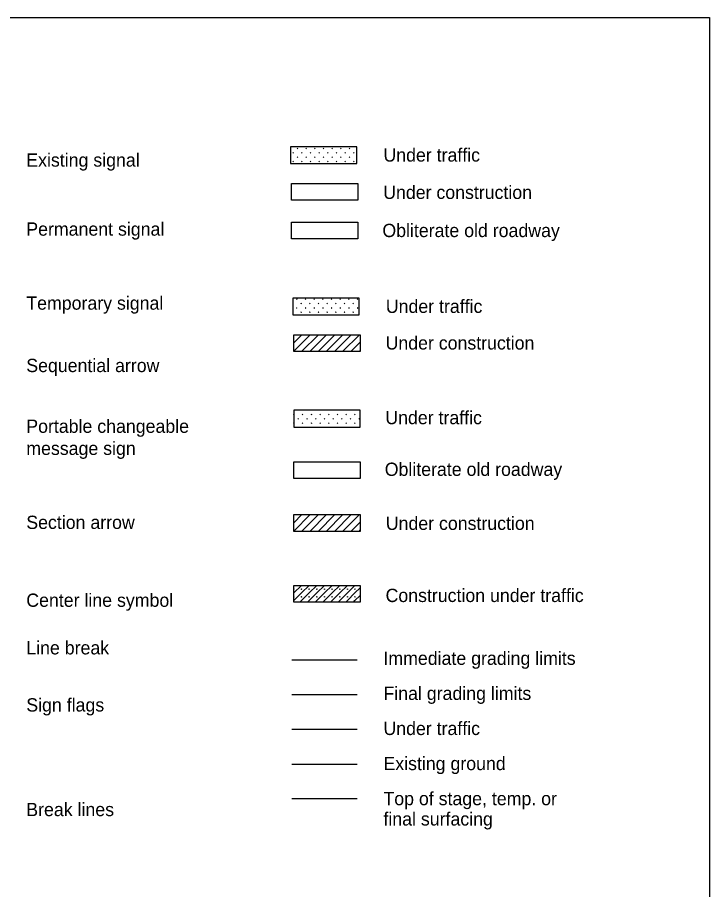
# Model space of a CAD drawing. Extents: x 1458 to 4498, y 17709 to 24109.
# Drawn here: x 3716 to 4498, y 18723 to 19709 of the extents above; entities that cross this region are included whole.
import ezdxf

# ---------------------------------------------------------------- set-up
doc = ezdxf.new("R2010")
doc.units = 0
doc.layers.add('P_TRAF_TCP_General', color=7, linetype='Continuous')
doc.layers.add('P_TRAF_TCP_GeneralTx', color=7, linetype='Continuous')

msp = doc.modelspace()

# ---------------------------------------------------------------- linework, layer by layer
at = {"layer": 'P_TRAF_TCP_General'}
for p, q in [((4027.54, 19555.92), (4027.19, 19556.28)), ((4027.54, 19555.92), (4027.19, 19555.57)), ((4027.54, 19555.92), (4027.89, 19556.28)), ((4027.54, 19555.92), (4027.89, 19555.57)), ((4032.11, 19561.2), (4032.81, 19560.49)), ((4032.81, 19561.2), (4032.11, 19560.49)), ((4037.38, 19555.92), (4037.03, 19556.28)), ((4037.38, 19555.92), (4037.03, 19555.57)), ((4037.38, 19555.92), (4037.73, 19556.28)), ((4037.38, 19555.92), (4037.73, 19555.57)), ((4041.95, 19561.2), (4042.65, 19560.49)), ((4042.65, 19561.2), (4041.95, 19560.49)), ((4047.22, 19555.92), (4046.87, 19556.28)), ((4047.22, 19555.92), (4046.87, 19555.57)), ((4047.22, 19555.92), (4047.57, 19556.28)), ((4047.22, 19555.92), (4047.57, 19555.57)), ((4051.78, 19561.2), (4052.49, 19560.49)), ((4052.49, 19561.2), (4051.78, 19560.49)), ((4057.06, 19555.92), (4056.7, 19556.28)), ((4057.06, 19555.92), (4056.7, 19555.57)), ((4057.06, 19555.92), (4057.41, 19556.28)), ((4057.06, 19555.92), (4057.41, 19555.57)), ((4061.62, 19561.2), (4062.33, 19560.49)), ((4062.33, 19561.2), (4061.62, 19560.49)), ((4066.9, 19555.92), (4066.54, 19556.28)), ((4066.9, 19555.92), (4066.54, 19555.57)), ((4066.9, 19555.92), (4067.25, 19556.28)), ((4066.9, 19555.92), (4067.25, 19555.57)), ((4071.46, 19561.2), (4072.17, 19560.49)), ((4072.17, 19561.2), (4071.46, 19560.49)), ((4076.73, 19555.92), (4076.38, 19556.28)), ((4076.73, 19555.92), (4076.38, 19555.57)), ((4076.73, 19555.92), (4077.09, 19556.28)), ((4076.73, 19555.92), (4077.09, 19555.57)), ((4081.3, 19561.2), (4082.01, 19560.49)), ((4082.01, 19561.2), (4081.3, 19560.49)), ((4086.57, 19555.92), (4086.22, 19556.28)), ((4086.57, 19555.92), (4086.22, 19555.57)), ((4086.57, 19555.92), (4086.93, 19556.28)), ((4086.57, 19555.92), (4086.93, 19555.57)), ((4091.14, 19561.2), (4091.85, 19560.49)), ((4091.85, 19561.2), (4091.14, 19560.49)), ((4096.41, 19555.92), (4096.06, 19556.28)), ((4096.41, 19555.92), (4096.06, 19555.57)), ((4096.41, 19555.92), (4096.76, 19556.28)), ((4096.41, 19555.92), (4096.76, 19555.57)), ((4027.54, 19546.09), (4027.19, 19546.44)), ((4027.54, 19546.09), (4027.19, 19545.73)), ((4027.54, 19546.09), (4027.89, 19546.44)), ((4027.54, 19546.09), (4027.89, 19545.73)), ((4032.11, 19551.36), (4032.81, 19550.65)), ((4032.81, 19551.36), (4032.11, 19550.65)), ((4037.38, 19546.09), (4037.03, 19546.44)), ((4037.38, 19546.09), (4037.03, 19545.73)), ((4037.38, 19546.09), (4037.73, 19546.44)), ((4037.38, 19546.09), (4037.73, 19545.73)), ((4041.95, 19551.36), (4042.65, 19550.65)), ((4042.65, 19551.36), (4041.95, 19550.65)), ((4047.22, 19546.09), (4046.87, 19546.44)), ((4047.22, 19546.09), (4046.87, 19545.73)), ((4047.22, 19546.09), (4047.57, 19546.44)), ((4047.22, 19546.09), (4047.57, 19545.73)), ((4051.78, 19551.36), (4052.49, 19550.65)), ((4052.49, 19551.36), (4051.78, 19550.65)), ((4057.06, 19546.09), (4056.7, 19546.44)), ((4057.06, 19546.09), (4056.7, 19545.73)), ((4057.06, 19546.09), (4057.41, 19546.44)), ((4057.06, 19546.09), (4057.41, 19545.73)), ((4061.62, 19551.36), (4062.33, 19550.65)), ((4062.33, 19551.36), (4061.62, 19550.65)), ((4066.9, 19546.09), (4066.54, 19546.44)), ((4066.9, 19546.09), (4066.54, 19545.73)), ((4066.9, 19546.09), (4067.25, 19546.44)), ((4066.9, 19546.09), (4067.25, 19545.73)), ((4071.46, 19551.36), (4072.17, 19550.65)), ((4072.17, 19551.36), (4071.46, 19550.65)), ((4076.73, 19546.09), (4076.38, 19546.44)), ((4076.73, 19546.09), (4076.38, 19545.73)), ((4076.73, 19546.09), (4077.09, 19546.44)), ((4076.73, 19546.09), (4077.09, 19545.73)), ((4081.3, 19551.36), (4082.01, 19550.65)), ((4082.01, 19551.36), (4081.3, 19550.65)), ((4086.57, 19546.09), (4086.22, 19546.44)), ((4086.57, 19546.09), (4086.22, 19545.73)), ((4086.57, 19546.09), (4086.93, 19546.44)), ((4086.57, 19546.09), (4086.93, 19545.73)), ((4091.14, 19551.36), (4091.85, 19550.65)), ((4091.85, 19551.36), (4091.14, 19550.65)), ((4096.41, 19546.09), (4096.06, 19546.44)), ((4096.41, 19546.09), (4096.06, 19545.73)), ((4096.41, 19546.09), (4096.76, 19546.44)), ((4096.41, 19546.09), (4096.76, 19545.73)), ((4031.3, 19390.81), (4032, 19390.11)), ((4032, 19390.81), (4031.3, 19390.11)), ((4041.14, 19390.81), (4041.84, 19390.11)), ((4041.84, 19390.81), (4041.14, 19390.11)), ((4050.97, 19390.81), (4051.68, 19390.11)), ((4051.68, 19390.81), (4050.97, 19390.11)), ((4060.81, 19390.81), (4061.52, 19390.11)), ((4061.52, 19390.81), (4060.81, 19390.11)), ((4070.65, 19390.81), (4071.36, 19390.11)), ((4071.36, 19390.81), (4070.65, 19390.11)), ((4080.49, 19390.81), (4081.2, 19390.11)), ((4081.2, 19390.81), (4080.49, 19390.11)), ((4090.33, 19390.81), (4091.04, 19390.11)), ((4091.04, 19390.81), (4090.33, 19390.11)), ((4100.17, 19390.81), (4100.87, 19390.11)), ((4100.87, 19390.81), (4100.17, 19390.11)), ((4031.3, 19380.97), (4032, 19380.27)), ((4032, 19380.97), (4031.3, 19380.27)), ((4036.57, 19385.54), (4036.22, 19385.89)), ((4036.57, 19385.54), (4036.22, 19385.19)), ((4036.57, 19385.54), (4036.92, 19385.89)), ((4036.57, 19385.54), (4036.92, 19385.19)), ((4041.14, 19380.97), (4041.84, 19380.27)), ((4041.84, 19380.97), (4041.14, 19380.27)), ((4046.41, 19385.54), (4046.06, 19385.89)), ((4046.41, 19385.54), (4046.06, 19385.19)), ((4046.41, 19385.54), (4046.76, 19385.89)), ((4046.41, 19385.54), (4046.76, 19385.19)), ((4050.97, 19380.97), (4051.68, 19380.27)), ((4051.68, 19380.97), (4050.97, 19380.27)), ((4056.25, 19385.54), (4055.89, 19385.89)), ((4056.25, 19385.54), (4055.89, 19385.19)), ((4056.25, 19385.54), (4056.6, 19385.89)), ((4056.25, 19385.54), (4056.6, 19385.19)), ((4060.81, 19380.97), (4061.52, 19380.27)), ((4061.52, 19380.97), (4060.81, 19380.27)), ((4066.09, 19385.54), (4065.73, 19385.89)), ((4066.09, 19385.54), (4065.73, 19385.19)), ((4066.09, 19385.54), (4066.44, 19385.89)), ((4066.09, 19385.54), (4066.44, 19385.19)), ((4070.65, 19380.97), (4071.36, 19380.27)), ((4071.36, 19380.97), (4070.65, 19380.27)), ((4075.92, 19385.54), (4075.57, 19385.89)), ((4075.92, 19385.54), (4075.57, 19385.19)), ((4075.92, 19385.54), (4076.28, 19385.89)), ((4075.92, 19385.54), (4076.28, 19385.19)), ((4080.49, 19380.97), (4081.2, 19380.27)), ((4081.2, 19380.97), (4080.49, 19380.27)), ((4085.76, 19385.54), (4085.41, 19385.89)), ((4085.76, 19385.54), (4085.41, 19385.19)), ((4085.76, 19385.54), (4086.12, 19385.89)), ((4085.76, 19385.54), (4086.12, 19385.19)), ((4090.33, 19380.97), (4091.04, 19380.27)), ((4091.04, 19380.97), (4090.33, 19380.27)), ((4095.6, 19385.54), (4095.25, 19385.89)), ((4095.6, 19385.54), (4095.25, 19385.19)), ((4095.6, 19385.54), (4095.96, 19385.89)), ((4095.6, 19385.54), (4095.96, 19385.19)), ((4100.17, 19380.97), (4100.87, 19380.27)), ((4100.87, 19380.97), (4100.17, 19380.27)), ((4036.57, 19375.7), (4036.22, 19376.05)), ((4036.57, 19375.7), (4036.22, 19375.35)), ((4036.57, 19375.7), (4036.92, 19376.05)), ((4036.57, 19375.7), (4036.92, 19375.35)), ((4046.41, 19375.7), (4046.06, 19376.05)), ((4046.41, 19375.7), (4046.06, 19375.35)), ((4046.41, 19375.7), (4046.76, 19376.05)), ((4046.41, 19375.7), (4046.76, 19375.35)), ((4056.25, 19375.7), (4055.89, 19376.05)), ((4056.25, 19375.7), (4055.89, 19375.35)), ((4056.25, 19375.7), (4056.6, 19376.05)), ((4056.25, 19375.7), (4056.6, 19375.35)), ((4066.09, 19375.7), (4065.73, 19376.05)), ((4066.09, 19375.7), (4065.73, 19375.35)), ((4066.09, 19375.7), (4066.44, 19376.05)), ((4066.09, 19375.7), (4066.44, 19375.35)), ((4075.92, 19375.7), (4075.57, 19376.05)), ((4075.92, 19375.7), (4075.57, 19375.35)), ((4075.92, 19375.7), (4076.28, 19376.05)), ((4075.92, 19375.7), (4076.28, 19375.35)), ((4085.76, 19375.7), (4085.41, 19376.05)), ((4085.76, 19375.7), (4085.41, 19375.35)), ((4085.76, 19375.7), (4086.12, 19376.05)), ((4085.76, 19375.7), (4086.12, 19375.35)), ((4095.6, 19375.7), (4095.25, 19376.05)), ((4095.6, 19375.7), (4095.25, 19375.35)), ((4095.6, 19375.7), (4095.96, 19376.05)), ((4095.6, 19375.7), (4095.96, 19375.35)), ((4028.36, 19350.42), (4028.36, 19350.42)), ((4028.36, 19341.14), (4037.63, 19350.42)), ((4028.36, 19331.87), (4046.9, 19350.42)), ((4037.22, 19331.46), (4056.18, 19350.42)), ((4046.5, 19331.46), (4065.45, 19350.42)), ((4055.77, 19331.46), (4074.72, 19350.42)), ((4065.04, 19331.46), (4084, 19350.42)), ((4074.32, 19331.46), (4093.27, 19350.42)), ((4083.59, 19331.46), (4102.54, 19350.42)), ((4092.86, 19331.46), (4103.32, 19341.92)), ((4102.14, 19331.46), (4103.32, 19332.65)), ((4028.57, 19260.25), (4028.36, 19260.46)), ((4028.57, 19260.25), (4028.36, 19260.04)), ((4028.57, 19260.25), (4028.92, 19260.6)), ((4028.57, 19260.25), (4028.92, 19259.9)), ((4038.4, 19260.25), (4038.05, 19260.6)), ((4038.4, 19260.25), (4038.05, 19259.9)), ((4038.4, 19260.25), (4038.76, 19260.6)), ((4038.4, 19260.25), (4038.76, 19259.9)), ((4048.24, 19260.25), (4047.89, 19260.6)), ((4048.24, 19260.25), (4047.89, 19259.9)), ((4048.24, 19260.25), (4048.6, 19260.6)), ((4048.24, 19260.25), (4048.6, 19259.9)), ((4058.08, 19260.25), (4057.73, 19260.6)), ((4058.08, 19260.25), (4057.73, 19259.9)), ((4058.08, 19260.25), (4058.43, 19260.6)), ((4058.08, 19260.25), (4058.43, 19259.9)), ((4067.92, 19260.25), (4067.57, 19260.6)), ((4067.92, 19260.25), (4067.57, 19259.9)), ((4067.92, 19260.25), (4068.27, 19260.6)), ((4067.92, 19260.25), (4068.27, 19259.9)), ((4077.76, 19260.25), (4077.41, 19260.6)), ((4077.76, 19260.25), (4077.41, 19259.9)), ((4077.76, 19260.25), (4078.11, 19260.6)), ((4077.76, 19260.25), (4078.11, 19259.9)), ((4087.6, 19260.25), (4087.24, 19260.6)), ((4087.6, 19260.25), (4087.24, 19259.9)), ((4087.6, 19260.25), (4087.95, 19260.6)), ((4087.6, 19260.25), (4087.95, 19259.9)), ((4097.44, 19260.25), (4097.08, 19260.6)), ((4097.44, 19260.25), (4097.08, 19259.9)), ((4097.44, 19260.25), (4097.79, 19260.6)), ((4097.44, 19260.25), (4097.79, 19259.9)), ((4028.57, 19250.41), (4028.36, 19250.62)), ((4028.57, 19250.41), (4028.36, 19250.2)), ((4028.57, 19250.41), (4028.92, 19250.76)), ((4028.57, 19250.41), (4028.92, 19250.06)), ((4033.13, 19255.68), (4033.84, 19254.98)), ((4033.84, 19255.68), (4033.13, 19254.98)), ((4038.4, 19250.41), (4038.05, 19250.76)), ((4038.4, 19250.41), (4038.05, 19250.06)), ((4038.4, 19250.41), (4038.76, 19250.76)), ((4038.4, 19250.41), (4038.76, 19250.06)), ((4042.97, 19255.68), (4043.68, 19254.98)), ((4043.68, 19255.68), (4042.97, 19254.98)), ((4048.24, 19250.41), (4047.89, 19250.76)), ((4048.24, 19250.41), (4047.89, 19250.06)), ((4048.24, 19250.41), (4048.6, 19250.76)), ((4048.24, 19250.41), (4048.6, 19250.06)), ((4052.81, 19255.68), (4053.51, 19254.98)), ((4053.51, 19255.68), (4052.81, 19254.98)), ((4058.08, 19250.41), (4057.73, 19250.76)), ((4058.08, 19250.41), (4057.73, 19250.06)), ((4058.08, 19250.41), (4058.43, 19250.76)), ((4058.08, 19250.41), (4058.43, 19250.06)), ((4062.65, 19255.68), (4063.35, 19254.98)), ((4063.35, 19255.68), (4062.65, 19254.98)), ((4067.92, 19250.41), (4067.57, 19250.76)), ((4067.92, 19250.41), (4067.57, 19250.06)), ((4067.92, 19250.41), (4068.27, 19250.76)), ((4067.92, 19250.41), (4068.27, 19250.06)), ((4072.49, 19255.68), (4073.19, 19254.98)), ((4073.19, 19255.68), (4072.49, 19254.98)), ((4077.76, 19250.41), (4077.41, 19250.76)), ((4077.76, 19250.41), (4077.41, 19250.06)), ((4077.76, 19250.41), (4078.11, 19250.76)), ((4077.76, 19250.41), (4078.11, 19250.06)), ((4082.32, 19255.68), (4083.03, 19254.98)), ((4083.03, 19255.68), (4082.32, 19254.98)), ((4087.6, 19250.41), (4087.24, 19250.76)), ((4087.6, 19250.41), (4087.24, 19250.06)), ((4087.6, 19250.41), (4087.95, 19250.76)), ((4087.6, 19250.41), (4087.95, 19250.06)), ((4092.16, 19255.68), (4092.87, 19254.98)), ((4092.87, 19255.68), (4092.16, 19254.98)), ((4097.44, 19250.41), (4097.08, 19250.76)), ((4097.44, 19250.41), (4097.08, 19250.06)), ((4097.44, 19250.41), (4097.79, 19250.76)), ((4097.44, 19250.41), (4097.79, 19250.06)), ((4102, 19255.68), (4102.71, 19254.98)), ((4102.71, 19255.68), (4102, 19254.98)), ((4028.36, 19146.99), (4028.36, 19146.99)), ((4028.36, 19137.72), (4037.63, 19146.99)), ((4028.36, 19128.44), (4046.9, 19146.99)), ((4037.22, 19128.03), (4056.18, 19146.99)), ((4046.5, 19128.03), (4065.45, 19146.99)), ((4055.77, 19128.03), (4074.72, 19146.99)), ((4065.04, 19128.03), (4084, 19146.99)), ((4074.32, 19128.03), (4093.27, 19146.99)), ((4083.59, 19128.03), (4102.54, 19146.99)), ((4092.86, 19128.03), (4103.32, 19138.49)), ((4102.14, 19128.03), (4103.32, 19129.22)), ((4028.36, 19058.36), (4037.01, 19067.01)), ((4028.36, 19063.01), (4028.68, 19062.68)), ((4028.36, 19062.35), (4028.36, 19063.01)), ((4028.68, 19062.68), (4028.36, 19062.35)), ((4036.68, 19062.68), (4037.01, 19063.01)), ((4037.01, 19062.35), (4036.68, 19062.68)), ((4037.01, 19058.36), (4045.66, 19067.01)), ((4037.01, 19063.01), (4037.34, 19062.68)), ((4037.01, 19062.35), (4037.01, 19063.01)), ((4037.01, 19062.35), (4037.01, 19063.01)), ((4037.34, 19062.68), (4037.01, 19062.35)), ((4045.33, 19062.68), (4045.66, 19063.01)), ((4045.66, 19062.35), (4045.33, 19062.68)), ((4045.66, 19058.36), (4054.31, 19067.01)), ((4045.66, 19063.01), (4045.99, 19062.68)), ((4045.66, 19062.35), (4045.66, 19063.01)), ((4045.66, 19062.35), (4045.66, 19063.01)), ((4045.99, 19062.68), (4045.66, 19062.35)), ((4053.99, 19062.68), (4054.31, 19063.01)), ((4054.31, 19062.35), (4053.99, 19062.68)), ((4054.31, 19058.36), (4062.97, 19067.01)), ((4054.31, 19063.01), (4054.64, 19062.68)), ((4054.31, 19062.35), (4054.31, 19063.01)), ((4054.31, 19062.35), (4054.31, 19063.01)), ((4054.64, 19062.68), (4054.31, 19062.35)), ((4062.64, 19062.68), (4062.97, 19063.01)), ((4062.97, 19062.35), (4062.64, 19062.68)), ((4062.97, 19058.36), (4071.62, 19067.01)), ((4062.97, 19063.01), (4063.3, 19062.68)), ((4062.97, 19062.35), (4062.97, 19063.01)), ((4062.97, 19062.35), (4062.97, 19063.01)), ((4063.3, 19062.68), (4062.97, 19062.35)), ((4071.29, 19062.68), (4071.62, 19063.01)), ((4071.62, 19062.35), (4071.29, 19062.68)), ((4071.62, 19058.36), (4080.27, 19067.01)), ((4071.62, 19063.01), (4071.95, 19062.68)), ((4071.62, 19062.35), (4071.62, 19063.01)), ((4071.62, 19062.35), (4071.62, 19063.01)), ((4071.95, 19062.68), (4071.62, 19062.35)), ((4079.94, 19062.68), (4080.27, 19063.01)), ((4080.27, 19062.35), (4079.94, 19062.68)), ((4080.27, 19058.36), (4088.93, 19067.01)), ((4080.27, 19063.01), (4080.6, 19062.68)), ((4080.27, 19062.35), (4080.27, 19063.01)), ((4080.27, 19062.35), (4080.27, 19063.01)), ((4080.6, 19062.68), (4080.27, 19062.35)), ((4088.6, 19062.68), (4088.93, 19063.01)), ((4088.93, 19062.35), (4088.6, 19062.68)), ((4088.93, 19058.36), (4097.58, 19067.01)), ((4088.93, 19063.01), (4089.25, 19062.68)), ((4088.93, 19062.35), (4088.93, 19063.01)), ((4088.93, 19062.35), (4088.93, 19063.01)), ((4089.25, 19062.68), (4088.93, 19062.35)), ((4097.25, 19062.68), (4097.58, 19063.01)), ((4097.58, 19062.35), (4097.25, 19062.68)), ((4097.58, 19058.36), (4103.32, 19064.1)), ((4097.58, 19063.01), (4097.91, 19062.68)), ((4097.58, 19062.35), (4097.58, 19063.01)), ((4097.58, 19062.35), (4097.58, 19063.01)), ((4097.91, 19062.68), (4097.58, 19062.35)), ((4028.36, 19049.7), (4037.01, 19058.36)), ((4028.36, 19054.36), (4028.68, 19054.03)), ((4028.36, 19053.7), (4028.36, 19054.36)), ((4028.68, 19054.03), (4028.36, 19053.7)), ((4036.68, 19054.03), (4037.01, 19054.36)), ((4037.01, 19053.7), (4036.68, 19054.03)), ((4037.01, 19049.7), (4045.66, 19058.36)), ((4037.01, 19054.36), (4037.34, 19054.03)), ((4037.01, 19053.7), (4037.01, 19054.36)), ((4037.01, 19053.7), (4037.01, 19054.36)), ((4037.34, 19054.03), (4037.01, 19053.7)), ((4045.33, 19054.03), (4045.66, 19054.36)), ((4045.66, 19053.7), (4045.33, 19054.03)), ((4045.66, 19049.7), (4054.31, 19058.36)), ((4045.66, 19054.36), (4045.99, 19054.03)), ((4045.66, 19053.7), (4045.66, 19054.36)), ((4045.66, 19053.7), (4045.66, 19054.36)), ((4045.99, 19054.03), (4045.66, 19053.7)), ((4053.99, 19054.03), (4054.31, 19054.36)), ((4054.31, 19053.7), (4053.99, 19054.03)), ((4054.31, 19049.7), (4062.97, 19058.36)), ((4054.31, 19054.36), (4054.64, 19054.03)), ((4054.31, 19053.7), (4054.31, 19054.36)), ((4054.31, 19053.7), (4054.31, 19054.36)), ((4054.64, 19054.03), (4054.31, 19053.7)), ((4062.64, 19054.03), (4062.97, 19054.36)), ((4062.97, 19053.7), (4062.64, 19054.03)), ((4062.97, 19049.7), (4071.62, 19058.36)), ((4062.97, 19054.36), (4063.3, 19054.03)), ((4062.97, 19053.7), (4062.97, 19054.36)), ((4062.97, 19053.7), (4062.97, 19054.36)), ((4063.3, 19054.03), (4062.97, 19053.7)), ((4071.29, 19054.03), (4071.62, 19054.36)), ((4071.62, 19053.7), (4071.29, 19054.03)), ((4071.62, 19049.7), (4080.27, 19058.36)), ((4071.62, 19054.36), (4071.95, 19054.03)), ((4071.62, 19053.7), (4071.62, 19054.36)), ((4071.62, 19053.7), (4071.62, 19054.36)), ((4071.95, 19054.03), (4071.62, 19053.7)), ((4079.94, 19054.03), (4080.27, 19054.36)), ((4080.27, 19053.7), (4079.94, 19054.03)), ((4080.27, 19049.7), (4088.93, 19058.36)), ((4080.27, 19054.36), (4080.6, 19054.03)), ((4080.27, 19053.7), (4080.27, 19054.36)), ((4080.27, 19053.7), (4080.27, 19054.36)), ((4080.6, 19054.03), (4080.27, 19053.7)), ((4088.6, 19054.03), (4088.93, 19054.36)), ((4088.93, 19053.7), (4088.6, 19054.03)), ((4088.93, 19049.7), (4097.58, 19058.36)), ((4088.93, 19054.36), (4089.25, 19054.03)), ((4088.93, 19053.7), (4088.93, 19054.36)), ((4088.93, 19053.7), (4088.93, 19054.36)), ((4089.25, 19054.03), (4088.93, 19053.7)), ((4097.25, 19054.03), (4097.58, 19054.36)), ((4097.58, 19053.7), (4097.25, 19054.03)), ((4097.58, 19049.7), (4103.32, 19055.45)), ((4097.58, 19054.36), (4097.91, 19054.03)), ((4097.58, 19053.7), (4097.58, 19054.36)), ((4097.58, 19053.7), (4097.58, 19054.36)), ((4097.91, 19054.03), (4097.58, 19053.7)), ((4035.36, 19048.06), (4037.01, 19049.7)), ((4044.01, 19048.06), (4045.66, 19049.7)), ((4052.67, 19048.06), (4054.31, 19049.7)), ((4061.32, 19048.06), (4062.97, 19049.7)), ((4069.97, 19048.06), (4071.62, 19049.7)), ((4078.62, 19048.06), (4080.27, 19049.7)), ((4087.28, 19048.06), (4088.93, 19049.7)), ((4095.93, 19048.06), (4097.58, 19049.7)), ((4026.36, 18982.63), (4099.91, 18982.63)), ((4026.36, 18943.41), (4099.91, 18943.41)), ((4026.36, 18904.2), (4099.91, 18904.2)), ((4026.36, 18864.99), (4099.91, 18864.99)), ((4026.36, 18825.87), (4099.91, 18825.87))]:
    msp.add_line(p, q, dxfattribs=at)
for points in [[(1458.44, 19709.14), (4498.44, 19709.14), (4498.44, 17709.14), (1458.44, 17709.14)], [(4024.55, 19562.83), (4024.55, 19543.87), (4099.52, 19543.87), (4099.52, 19562.83)], [(4025.68, 19521.53), (4100.65, 19521.53), (4100.65, 19502.57), (4025.68, 19502.57)], [(4100.65, 19521.53), (4100.65, 19502.57), (4025.68, 19502.57), (4025.68, 19521.53)], [(4025.68, 19477.6), (4100.65, 19477.6), (4100.65, 19458.65), (4025.68, 19458.65)], [(4100.65, 19477.6), (4100.65, 19458.65), (4025.68, 19458.65), (4025.68, 19477.6)], [(4027.22, 19391.72), (4027.22, 19372.77), (4102.19, 19372.77), (4102.19, 19391.72)], [(4028.36, 19350.42), (4103.32, 19350.42), (4103.32, 19331.46), (4028.36, 19331.46)], [(4028.36, 19264.92), (4028.36, 19245.97), (4103.32, 19245.97), (4103.32, 19264.92)], [(4103.32, 19206.61), (4103.32, 19187.66), (4028.36, 19187.66), (4028.36, 19206.61)], [(4028.36, 19206.61), (4103.32, 19206.61), (4103.32, 19187.66), (4028.36, 19187.66)], [(4028.36, 19146.99), (4103.32, 19146.99), (4103.32, 19128.03), (4028.36, 19128.03)], [(4028.36, 19067.01), (4103.32, 19067.01), (4103.32, 19048.06), (4028.36, 19048.06)]]:
    msp.add_lwpolyline(points, close=True, dxfattribs=at)

# ---------------------------------------------------------------- texts
for s, p in [('Under traffic', (4129.75, 19546.12)), ('Under construction', (4129.47, 19503.89)), ('Obliterate old roadway', (4128.54, 19460.78)), ('Under traffic', (4132.42, 19375.02)), ('Under construction', (4132.14, 19333.63)), ('Under traffic', (4131.88, 19249.2)), ('Obliterate old roadway', (4131.21, 19190.75)), ('Under construction', (4132.4, 19129.66)), ('Construction under traffic', (4132.14, 19048.13)), ('Immediate grading limits', (4129.75, 18977.09)), ('Final grading limits', (4129.75, 18937.41)), ('Under traffic', (4129.75, 18897.74)), ('Existing ground', (4129.75, 18858.07)), ('Top of stage, temp. or', (4129.75, 18818.39)), ('final surfacing', (4129.75, 18795.4))]:
    msp.add_text(s, height=14.994, dxfattribs=at).set_placement(p)
at = {"layer": 'P_TRAF_TCP_GeneralTx'}
for s, p in [('Existing signal', (3725.96, 19540.41)), ('Permanent signal', (3725.96, 19462.36)), ('Temporary signal', (3725.96, 19378.68)), ('Sequential arrow', (3725.96, 19308.12)), ('Portable changeable', (3725.96, 19239.43)), ('message sign', (3725.96, 19214.43)), ('Section arrow', (3725.96, 19130.77)), ('Center line symbol', (3725.96, 19042.71)), ('Line break', (3725.96, 18988.9)), ('Sign flags', (3725.96, 18924.33)), ('Break lines', (3725.96, 18806.04))]:
    msp.add_text(s, height=15, dxfattribs=at).set_placement(p)

doc.saveas('drawing.dxf')
